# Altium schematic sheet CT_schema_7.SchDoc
size 278 x 170 mm
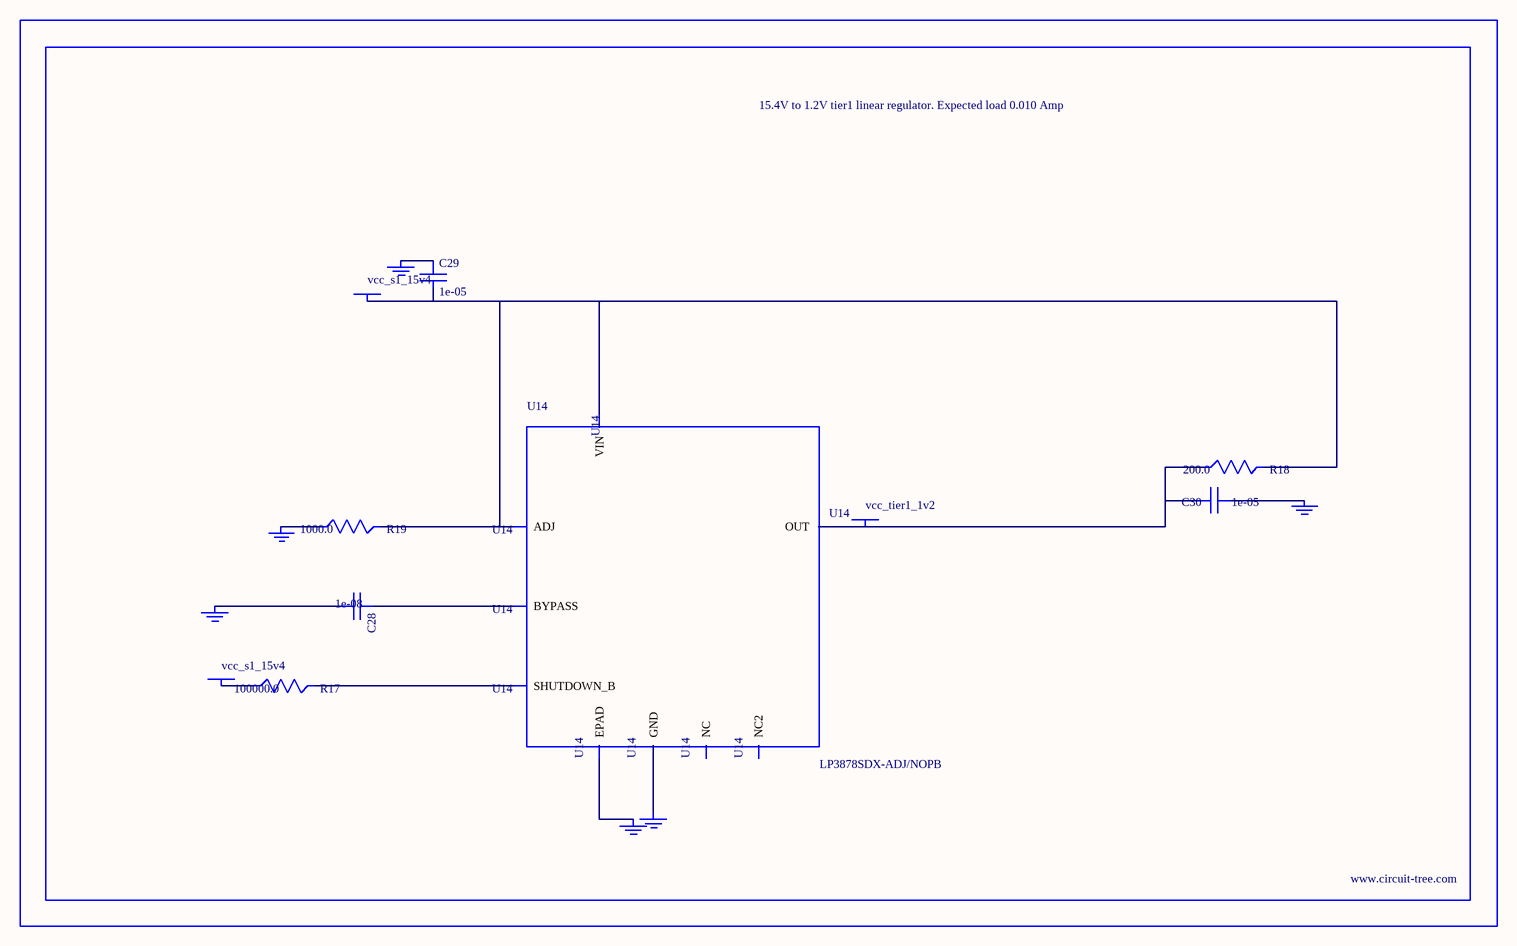
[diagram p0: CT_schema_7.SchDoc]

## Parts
BORDER6  (no value)
C28  1e-08  [C0402]
C29  1e-05  [C1210]
C30  1e-05  [C0805]
GND_INSTANCE_6_0  (no value)
GND_INSTANCE_6_1  (no value)
GND_INSTANCE_6_2  (no value)
GND_INSTANCE_6_3  (no value)
GND_INSTANCE_6_4  (no value)
GND_INSTANCE_6_5  (no value)
POWER_INSTANCE_6_0  vcc_s1_15v4
POWER_INSTANCE_6_1  vcc_s1_15v4
POWER_INSTANCE_6_2  vcc_tier1_1v2
R17  100000.0  [R0603]
R18  200.0  [R0603]
R19  1000.0  [R0603]
U14  LP3878SDX-ADJ/NOPB  [WSON-8]

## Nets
NetC28_1: C28.1 U14.1(BYPASS)
NetC28_2: C28.2 GND_INSTANCE_6_0.0(GND)
NetC29_1: C29.1 GND_INSTANCE_6_1.0(GND)
NetC29_2: C29.2 POWER_INSTANCE_6_0.0(PWR) R18.2 R19.2 U14.4(VIN) U14.6(ADJ)
NetC30_1: C30.1 GND_INSTANCE_6_2.0(GND)
NetC30_2: C30.2 POWER_INSTANCE_6_2.0(PWR) R18.1 U14.5(OUT)
NetGND_INSTANCE_6_3_0: GND_INSTANCE_6_3.0(GND) R19.1
NetGND_INSTANCE_6_4_0: GND_INSTANCE_6_4.0(GND) U14.PAD(EPAD)
NetGND_INSTANCE_6_5_0: GND_INSTANCE_6_5.0(GND) U14.3(GND)
NetPOWER_INSTANCE_6_1_0: POWER_INSTANCE_6_1.0(PWR) R17.1
NetR17_2: R17.2 U14.8(SHUTDOWN_B)

Not connected (* = marked no-connect by the designer): U14 2(NC) 7(NC2)

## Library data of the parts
BORDER6 = BORDER_PAGE6
C28 = C0402C103K3RAC
C29 = C1210C106K5PACTU
C30 = GRM219R60J106ME19D
GND_INSTANCE_6_0-GND_INSTANCE_6_5 = GND
POWER_INSTANCE_6_0-POWER_INSTANCE_6_2 = PWR
R17 = RC0603JR-07100KL
R18 = RC0603JR-07200RL
R19 = RC0603JR-071KL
